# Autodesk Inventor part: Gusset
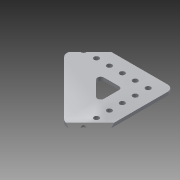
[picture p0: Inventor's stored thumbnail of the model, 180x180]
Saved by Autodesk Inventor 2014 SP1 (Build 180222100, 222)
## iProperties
Created: 2014-06
Part Number: Gusset
Material: Aluminum 6061
Document SubType Name: Sheet Metal
Designer: Michael
Density: 2.71 g/cm^3
Sheet Metal Rule: Default
Appearance: Aluminum - Flat
Mass: 39.8891 g
Surface Area: 109.572 cm^2
Volume: 14.7192 cm^3
Author: Michael
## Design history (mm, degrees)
node "Face1"
  sketch "Sketch1" dims "d10" = 25.4, "d17" = 25.4, "d30" = 25.4, "d37" = 25.4
    geometry: L1 (0, 0)-(0, 30.066); L2 (0, 0)-(37.896, 0); L3 (-12.7, 69.85)-(-12.7, -12.7); L4 (-12.7, -12.7)-(69.85, -12.7); L5 (-12.7, 69.85)-(12.7, 69.85); L6 (69.85, -12.7)-(69.85, 12.7); L7 (12.7, 69.85)-(12.7, 12.7); L8 (12.7, 12.7)-(69.85, 12.7); L9 (12.7, 69.85)-(69.85, 12.7); L10 (12.7, 38.419)-(38.419, 12.7); C1 r 2.489 at (0, 0); C2 r 2.489 at (12.7, 0); C3 r 2.489 at (25.4, 0); C4 r 2.489 at (38.1, 0); C5 r 2.489 at (50.8, 0); C6 r 2.489 at (0, 12.7); C7 r 2.489 at (0, 25.4); C8 r 2.489 at (0, 38.1); C9 r 2.489 at (0, 50.8); C10 r 2.489 at (63.5, 0); C11 r 2.489 at (76.2, 0); C12 r 2.489 at (88.9, 0); C13 r 2.489 at (0, 63.5); C14 r 2.489 at (0, 76.2); C15 r 2.489 at (0, 88.9); 3 further points
    constraints: 20 end point, 15 centre point, 5 perpendicular, 3 parallel, 3 vertical, 2 horizontal, 2 midpoint, 2 point on line, 1 coincident, 1 horizontal alignment, 1 vertical alignment, 28 other
    dimensions: "d1" = 4.9784 diameter of C1; "d7" = 12.7 distance of L1.start C2.centre; "d14" = 12.7 distance of L1.start C6.centre; "d21" = 25.4 distance of L3.start L5.end; "d22" = 25.4 distance of L4.end L6.end (= d21); "d27" = 12.7 distance of C5.centre C10.centre; "d34" = 12.7 distance of C9.centre C13.centre; "d41" = 22.225 distance between parallel lines of L9 L10; "d45" = 6.35 distance from line of C13.centre L5; "d46" = 6.35 distance from line of L6 C10.centre
feature "Corner Round1" dims "d43" = 3.175
feature "Corner Round2" dims "d44" = 6.35
body "Solid1"
face "Plate1" dims "Thickness" = 3.175 (derived)
other parameters: "d0" = 4.9784, "KFactor" = 4.4, "BendRadius" = 3.175 (= Thickness), "BendReliefWidth" = 3.175 (= Thickness), "BendReliefDepth" = 1.5875 (= 0.5 x Thickness), "CornerReliefSize" = 12.7 (= 4 x Thickness), "SeamGap" = 0.00508, "MinimumRemnant" = 6.35 (= 2 x Thickness), "TransitionRadius" = 3.175 (= BendRadius), "JacobiRadiusSize" = 3.175 (= Thickness), "GapSize" = 3.175 (= Thickness), "d42" = 3.175 (= BendRadius)
